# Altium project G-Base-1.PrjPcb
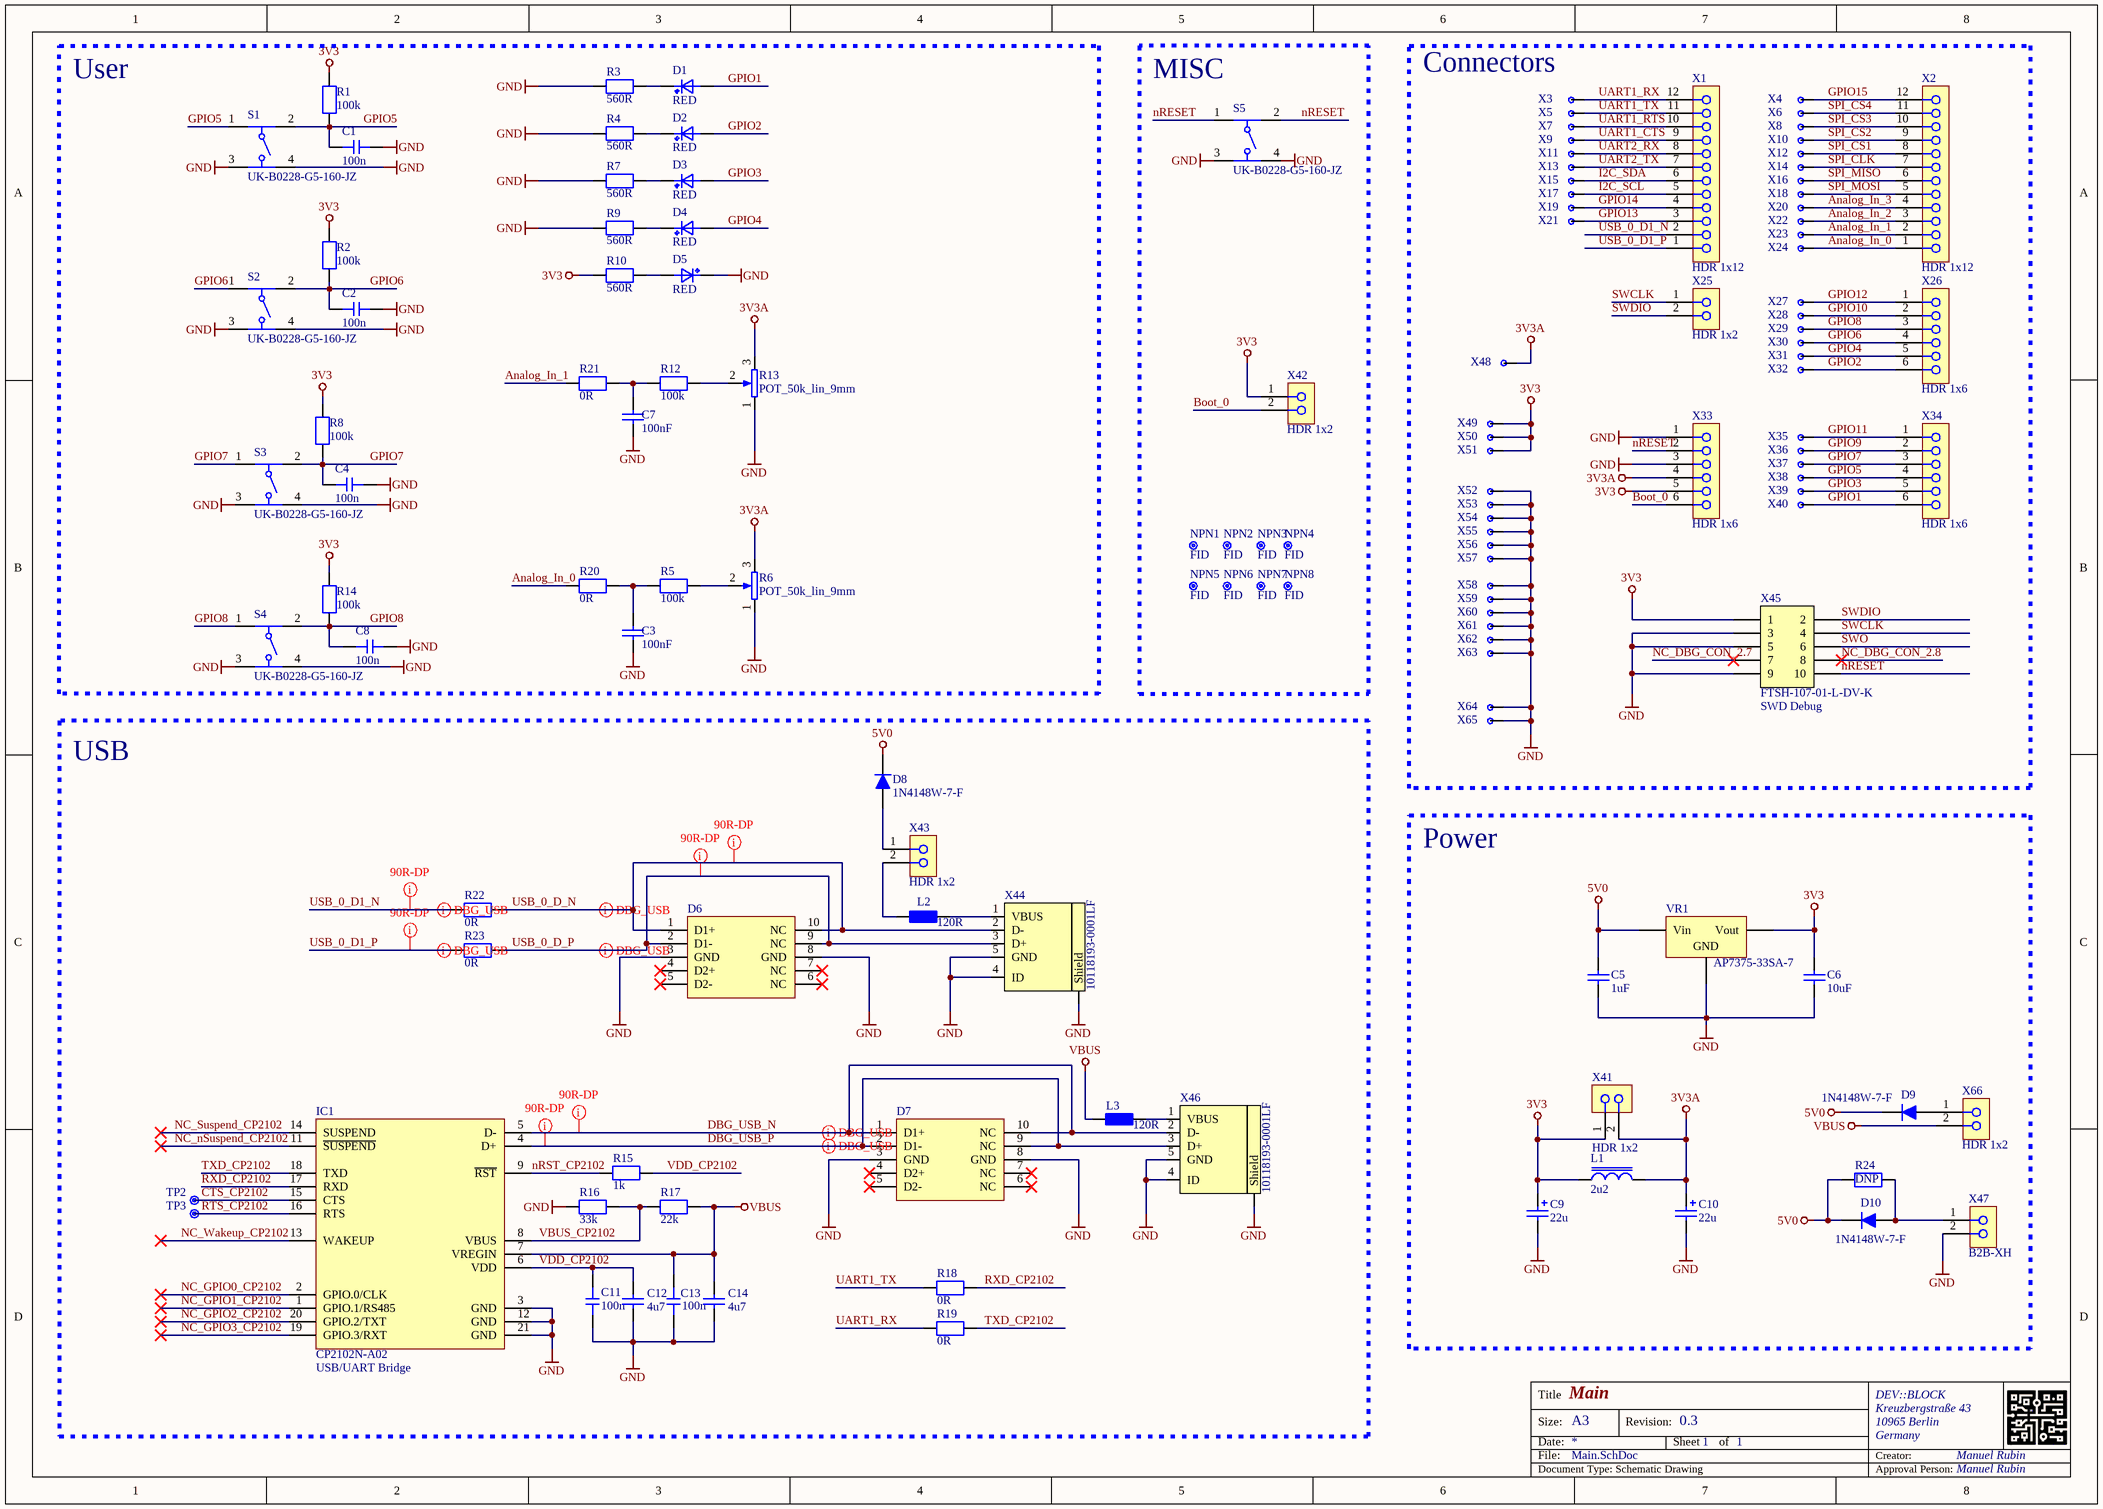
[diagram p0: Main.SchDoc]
Address2: Kreuzbergstraße 43; Address3: 10965 Berlin; Address4: Germany; ApprovalSchematic: Manuel Rubin; CompanyName: DEV::BLOCK; CreatorSchematic: Manuel Rubin; ProjectRevision: 0.3
1 sheet, 133 parts. Net scope: global (net labels, ports and power ports of the same name join across sheets).
Board file: erb-pcb0006.PcbDoc

## Sheet Main.SchDoc: Main
size A3; Author: Manuel Rubin; Revision: 0.1; SheetNumber: 1; SheetTotal: 1

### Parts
C1  100n  [CAPC1608X95N]
C2  100n  [CAPC1608X95N]
C3  100nF  [CAPC1608X95N]
C4  100n  [CAPC1608X95N]
C5  1uF  [CAPC2012X145N]
C6  10uF  [CAPC2012X145N]
C7  100nF  [CAPC1608X95N]
C8  100n  [CAPC1608X95N]
C9  22u  [CAPAE4643X54M]
C10  22u  [CAPAE4643X54M]
C11  100n  [CAPC1608X95N]
C12  4u7  [CAPC1608X95N]
C13  100n  [CAPC1608X95N]
C14  4u7  [CAPC1608X95N]
D1  RED  [WL-SMCW_0805]
D2  RED  [WL-SMCW_0805]
D3  RED  [WL-SMCW_0805]
D4  RED  [WL-SMCW_0805]
D5  RED  [WL-SMCW_0805]
D6  (no value)  [DQA R-PUSON-N10]
D7  (no value)  [DQA R-PUSON-N10]
D8  1N4148W-7-F  [SOD-123]
D9  1N4148W-7-F  [SOD-123]
D10  1N4148W-7-F  [SOD-123]
IC1  CP2102N-A02  DevNote: USB/UART Bridge  [SILABS_CP2102N-A02-GQFN20R]
L1  2u2  [INDP5050X39N]
L2  120R  [INDC1608X95AN]
L3  120R  [INDC1608X95AN]
NPN1  FID  [Fiducial_1mm]
NPN2  FID  [Fiducial_1mm]
NPN3  FID  [Fiducial_1mm]
NPN4  FID  [Fiducial_1mm]
NPN5  FID  [Fiducial_1mm]
NPN6  FID  [Fiducial_1mm]
NPN7  FID  [Fiducial_1mm]
NPN8  FID  [Fiducial_1mm]
R1  100k  [RESC2012X70N]
R2  100k  [RESC2012X70N]
R3  560R  [RESC1608X55N]
R4  560R  [RESC1608X55N]
R5  100k  [RESC2012X70N]
R6  POT_50k_lin_9mm  [PTV09]
R7  560R  [RESC1608X55N]
R8  100k  [RESC2012X70N]
R9  560R  [RESC1608X55N]
R10  560R  [RESC1608X55N]
R12  100k  [RESC2012X70N]
R13  POT_50k_lin_9mm  [PTV09]
R14  100k  [RESC2012X70N]
R15  1k  [RESC1608X55AN]
R16  33k  [RESC1608X55AN]
R17  22k  [RESC1608X55AN]
R18  0R  [RESC1608X55N]
R19  0R  [RESC1608X55N]
R20  0R  [RESC1608X55N]
R21  0R  [RESC1608X55N]
R22  0R  [RESC1608X55N]
R23  0R  [RESC1608X55N]
R24  DNP  [RESC2012X70N]  (no BOM)
S1  UK-B0228-G5-160-JZ  [UK-B0228-G5-160-JZ]
S2  UK-B0228-G5-160-JZ  [UK-B0228-G5-160-JZ]
S3  UK-B0228-G5-160-JZ  [UK-B0228-G5-160-JZ]
S4  UK-B0228-G5-160-JZ  [UK-B0228-G5-160-JZ]
S5  UK-B0228-G5-160-JZ  [UK-B0228-G5-160-JZ]
TP2  TP 0.7mm  [TP_0.7mm]  (value not drawn)  (no BOM)
TP3  TP 0.7mm  [TP_0.7mm]  (value not drawn)  (no BOM)
VR1  AP7375-33SA-7  [SOT95P280X135-3N_123]
X1  HDR 1x12  [61301211821_NO]
X2  HDR 1x12  [61301211821_NO]
X3  PAD  [PAD_1.1_1.6]  (value not drawn)  (net tie, no BOM)
X4  PAD  [PAD_1.1_1.6]  (value not drawn)  (net tie, no BOM)
X5  PAD  [PAD_1.1_1.6]  (value not drawn)  (net tie, no BOM)
X6  PAD  [PAD_1.1_1.6]  (value not drawn)  (net tie, no BOM)
X7  PAD  [PAD_1.1_1.6]  (value not drawn)  (net tie, no BOM)
X8  PAD  [PAD_1.1_1.6]  (value not drawn)  (net tie, no BOM)
X9  PAD  [PAD_1.1_1.6]  (value not drawn)  (net tie, no BOM)
X10  PAD  [PAD_1.1_1.6]  (value not drawn)  (net tie, no BOM)
X11  PAD  [PAD_1.1_1.6]  (value not drawn)  (net tie, no BOM)
X12  PAD  [PAD_1.1_1.6]  (value not drawn)  (net tie, no BOM)
X13  PAD  [PAD_1.1_1.6]  (value not drawn)  (net tie, no BOM)
X14  PAD  [PAD_1.1_1.6]  (value not drawn)  (net tie, no BOM)
X15  PAD  [PAD_1.1_1.6]  (value not drawn)  (net tie, no BOM)
X16  PAD  [PAD_1.1_1.6]  (value not drawn)  (net tie, no BOM)
X17  PAD  [PAD_1.1_1.6]  (value not drawn)  (net tie, no BOM)
X18  PAD  [PAD_1.1_1.6]  (value not drawn)  (net tie, no BOM)
X19  PAD  [PAD_1.1_1.6]  (value not drawn)  (net tie, no BOM)
X20  PAD  [PAD_1.1_1.6]  (value not drawn)  (net tie, no BOM)
X21  PAD  [PAD_1.1_1.6]  (value not drawn)  (net tie, no BOM)
X22  PAD  [PAD_1.1_1.6]  (value not drawn)  (net tie, no BOM)
X23  PAD  [PAD_1.1_1.6]  (value not drawn)  (net tie, no BOM)
X24  PAD  [PAD_1.1_1.6]  (value not drawn)  (net tie, no BOM)
X25  HDR 1x2  [61300211821_NO]
X26  HDR 1x6  [61300611821_NO]
X27  PAD  [PAD_1.1_1.6]  (value not drawn)  (net tie, no BOM)
X28  PAD  [PAD_1.1_1.6]  (value not drawn)  (net tie, no BOM)
X29  PAD  [PAD_1.1_1.6]  (value not drawn)  (net tie, no BOM)
X30  PAD  [PAD_1.1_1.6]  (value not drawn)  (net tie, no BOM)
X31  PAD  [PAD_1.1_1.6]  (value not drawn)  (net tie, no BOM)
X32  PAD  [PAD_1.1_1.6]  (value not drawn)  (net tie, no BOM)
X33  HDR 1x6  [61300611821_NO]
X34  HDR 1x6  [61300611821_NO]
X35  PAD  [PAD_1.1_1.6]  (value not drawn)  (net tie, no BOM)
X36  PAD  [PAD_1.1_1.6]  (value not drawn)  (net tie, no BOM)
X37  PAD  [PAD_1.1_1.6]  (value not drawn)  (net tie, no BOM)
X38  PAD  [PAD_1.1_1.6]  (value not drawn)  (net tie, no BOM)
X39  PAD  [PAD_1.1_1.6]  (value not drawn)  (net tie, no BOM)
X40  PAD  [PAD_1.1_1.6]  (value not drawn)  (net tie, no BOM)
X41  HDR 1x2  [CON_HEADER2.54_1x2W]
X42  HDR 1x2  [CON_HEADER2.54_1x2W]
X43  HDR 1x2  [CON_HEADER2.54_1x2W]
X44  10118193-0001LF  [USB-Micro-B-RA-SMD-PiP]
X45  FTSH-107-01-L-DV-K  DevNote: SWD Debug  [HDR_2x5-SMD-1.27mm-K]
X46  10118193-0001LF  [USB-Micro-B-RA-SMD-PiP]
X47  B2B-XH  [JST_B2B-XH-A_(LF)(SN)]
X48  PAD  [PAD_1.1_1.6]  (value not drawn)  (net tie, no BOM)
X49  PAD  [PAD_1.1_1.6]  (value not drawn)  (net tie, no BOM)
X50  PAD  [PAD_1.1_1.6]  (value not drawn)  (net tie, no BOM)
X51  PAD  [PAD_1.1_1.6]  (value not drawn)  (net tie, no BOM)
X52  PAD  [PAD_1.1_1.6]  (value not drawn)  (net tie, no BOM)
X53  PAD  [PAD_1.1_1.6]  (value not drawn)  (net tie, no BOM)
X54  PAD  [PAD_1.1_1.6]  (value not drawn)  (net tie, no BOM)
X55  PAD  [PAD_1.1_1.6]  (value not drawn)  (net tie, no BOM)
X56  PAD  [PAD_1.1_1.6]  (value not drawn)  (net tie, no BOM)
X57  PAD  [PAD_1.1_1.6]  (value not drawn)  (net tie, no BOM)
X58  PAD  [PAD_1.1_1.6]  (value not drawn)  (net tie, no BOM)
X59  PAD  [PAD_1.1_1.6]  (value not drawn)  (net tie, no BOM)
X60  PAD  [PAD_1.1_1.6]  (value not drawn)  (net tie, no BOM)
X61  PAD  [PAD_1.1_1.6]  (value not drawn)  (net tie, no BOM)
X62  PAD  [PAD_1.1_1.6]  (value not drawn)  (net tie, no BOM)
X63  PAD  [PAD_1.1_1.6]  (value not drawn)  (net tie, no BOM)
X64  PAD  [PAD_1.1_1.6]  (value not drawn)  (net tie, no BOM)
X65  PAD  [PAD_1.1_1.6]  (value not drawn)  (net tie, no BOM)
X66  HDR 1x2  [CON_HEADER2.54_1x2W]

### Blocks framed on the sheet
User: C1-C4 C7 C8 D1-D5 R1-R10 R12-R14 R20 R21 S1-S4
MISC: NPN1-NPN8 S5 X42
Connectors: X1-X40 X45 X48-X65
USB: C11-C14 D6-D8 IC1 L2 L3 R15-R19 R22 R23 TP2 TP3 X43 X44 X46
Power: C5 C6 C9 C10 D9 D10 L1 R24 VR1 X41 X47 X66

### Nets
3V3: C6.1 C9.1 L1.1 R1.2 R2.2 R8.2 R10.1 R14.2 VR1.2(Vout) X33.5 X41.1 X42.1 X45.1 X49.1 X50.1 X51.1
3V3A: C10.1 L1.2 R6.3 R13.3 X33.4 X41.2 X48.1
5V0: C5.1 D8.2(K) D9.2(K) D10.2(K) R24.1 VR1.1(Vin)
GND: C1.2 C2.2 C3.2 C4.2 C5.2 C6.2 C7.2 C8.2 C9.2 C10.2 C11.1 C12.1 C13.1 C14.1 D5.K D6.3(GND) D6.8(GND) D7.3(GND) D7.8(GND) IC1.3(GND) IC1.12(GND) IC1.21(GND) R3.1 R4.1 R6.1 R7.1 R9.1 R13.1 R16.2 S1.3 S1.4 S2.3 S2.4 S3.3 S3.4 S4.3 S4.4 S5.3 S5.4 VR1.3(GND) X33.1 X33.3 X44.4(ID) X44.5(GND) X44.6(Shield) X45.3 X45.5 X45.9 X46.4(ID) X46.5(GND) X46.6(Shield) X47.2 X52.1 X53.1 X54.1 X55.1 X56.1 X57.1 X58.1 X59.1 X60.1 X61.1 X62.1 X63.1 X64.1 X65.1
VBUS: C13.2 C14.2 IC1.7(VREGIN) L3.1 R17.1 X66.2
Analog_In_0: R20.2 X2.1 X24.1
Analog_In_1: R21.2 X2.2 X23.1
Analog_In_2: X2.3 X22.1
Analog_In_3: X2.4 X20.1
Boot_0: X33.6 X42.2
CTS_CP2102: IC1.15(CTS) TP2.1
DBG_USB_N: D7.1(D1+) D7.10(NC) IC1.5(D-) X46.2(D-)
DBG_USB_P: D7.2(D1-) D7.9(NC) IC1.4(D+) X46.3(D+)
GPIO1: D1.A X34.6 X40.1
GPIO2: D2.A X26.6 X32.1
GPIO3: D3.A X34.5 X39.1
GPIO4: D4.A X26.5 X31.1
GPIO5: C1.1 R1.1 S1.1 S1.2 X34.4 X38.1
GPIO6: C2.1 R2.1 S2.1 S2.2 X26.4 X30.1
GPIO7: C4.1 R8.1 S3.1 S3.2 X34.3 X37.1
GPIO8: C8.1 R14.1 S4.1 S4.2 X26.3 X29.1
GPIO9: X34.2 X36.1
GPIO10: X26.2 X28.1
GPIO11: X34.1 X35.1
GPIO12: X26.1 X27.1
GPIO13: X1.3 X21.1
GPIO14: X1.4 X19.1
GPIO15: X2.12 X4.1
I2C_SCL: X1.5 X17.1
I2C_SDA: X1.6 X15.1
NC_DBG_CON_2.7: X45.7
NC_DBG_CON_2.8: X45.8
NC_GPIO0_CP2102: IC1.2(GPIO.0/CLK)
NC_GPIO1_CP2102: IC1.1(GPIO.1/RS485)
NC_GPIO2_CP2102: IC1.20(GPIO.2/TXT)
NC_GPIO3_CP2102: IC1.19(GPIO.3/RXT)
NC_nSuspend_CP2102: IC1.11(~{SUSPEND})
NC_Suspend_CP2102: IC1.14(SUSPEND)
NC_Wakeup_CP2102: IC1.13(WAKEUP)
nRESET: S5.1 S5.2 X33.2 X45.10
nRST_CP2102: IC1.9(~{RST}) R15.2
RTS_CP2102: IC1.16(RTS) TP3.1
RXD_CP2102: IC1.17(RXD) R18.1
SPI_CLK: X2.7 X14.1
SPI_CS1: X2.8 X12.1
SPI_CS2: X2.9 X10.1
SPI_CS3: X2.10 X8.1
SPI_CS4: X2.11 X6.1
SPI_MISO: X2.6 X16.1
SPI_MOSI: X2.5 X18.1
SWCLK: X25.1 X45.4
SWDIO: X25.2 X45.2
SWO: X45.6
TXD_CP2102: IC1.18(TXD) R19.1
UART1_CTS: X1.9 X9.1
UART1_RTS: X1.10 X7.1
UART1_RX: R19.2 X1.12 X3.1
UART1_TX: R18.2 X1.11 X5.1
UART2_RX: X1.8 X11.1
UART2_TX: X1.7 X13.1
USB_0_D1_N: R22.2 X1.2
USB_0_D1_P: R23.2 X1.1
USB_0_D_N: D6.1(D1+) D6.10(NC) R22.1 X44.2(D-)
USB_0_D_P: D6.2(D1-) D6.9(NC) R23.1 X44.3(D+)
VBUS_CP2102: IC1.8(VBUS) R16.1 R17.2
VDD_CP2102: C11.2 C12.2 IC1.6(VDD) R15.1
NetC3_1: C3.1 R5.1 R20.1
NetC7_1: C7.1 R12.1 R21.1
NetD1_K: D1.K R3.2
NetD2_K: D2.K R4.2
NetD3_K: D3.K R7.2
NetD4_K: D4.K R9.2
NetD5_A: D5.A R10.2
NetD8_1: D8.1(A) X43.1
NetD9_1: D9.1(A) X66.1
NetD10_1: D10.1(A) R24.2 X47.1
NetL2_1: L2.1 X43.2
NetL2_2: L2.2 X44.1(VBUS)
NetL3_2: L3.2 X46.1(VBUS)
NetR5_2: R5.2 R6.2
NetR12_2: R12.2 R13.2

Not connected (* = marked no-connect by the designer): D6 4(D2+)* 5(D2-)* 6(NC)* 7(NC)*; D7 4(D2+)* 5(D2-)* 6(NC)* 7(NC)*

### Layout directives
differential pair: DBG_USB_N, DBG_USB_P, USB_0_D1_N, USB_0_D1_P, USB_0_D_N, USB_0_D_P
net class 90R-DP: DBG_USB_N, DBG_USB_P, USB_0_D1_N, USB_0_D1_P, USB_0_D_N, USB_0_D_P

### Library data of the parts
C1 C2 C4 C8 C11 C13 = C_100n_50V_0603: 100n_50V; Manufacturer: AVX; Manufacturer Part Number: 06031C104KAT2A; Voltage Rating: 50V; Tolerance: +-10%; Alternatives allowed: YES; Notes: X7R, 0603; Value: 100nF
C3 C7 = CAP_100nF_0603: Multilayer Ceramic Capacitors MLCC - SMD/SMT, 100nF; Manufacturer: YAGEO; Manufacturer Part Number: CC0603KRX7R9BB104; Voltage Rating: 50VDC; Tolerance: 10%; Alternatives allowed: yes
C5 = CAP_1uF_0805: Multilayer Ceramic Capacitors MLCC - SMD/SMT, 1uF; Manufacturer: Samsung Electro-Mechanics; Manufacturer Part Number: CL21B105KBFNNNE; Tolerance: 10%; Voltage Rating: 50V; Alternatives allowed: yes
C6 = CAP_10uF_0805: Multilayer Ceramic Capacitors MLCC - SMD/SMT, 10uF; Manufacturer: Samsung Electro-Mechanics; Manufacturer Part Number: CL21A106KAYNNNE; Tolerance: 10%; Voltage Rating: 25V; Alternatives allowed: yes
C9 C10 = CAP_22u: Aluminium Electrolytic Capacitors - SMD 22UF 16V HA SMD; Manufacturer: Panasonic; Manufacturer Part Number: EEE-HAC220WAR; Tolerance: 20%; Alternatives allowed: NO
C12 C14 = CAP_4u7_0603: 16V 4.7uF X5R ±10% 0603 Multilayer Ceramic Capacitors MLCC - SMD/SMT ROHS; Manufacturer: Murata Electronics; Manufacturer Part Number: GRM188C81C475KE11D; Voltage Rating: 16VDC; Alternatives allowed: yes
D1 = LED_0805_RED_AK: Standard LEDs - SMD WL-SMCW SMDMono TpVw Waterclr 0805 Red; Manufacturer: Wurth Elektronik; Manufacturer Part Number: 150080RS75000; Voltage Rating: 2.0; Alternatives allowed: YES; DevNote: LED1
D2 = LED_0805_RED_AK: Standard LEDs - SMD WL-SMCW SMDMono TpVw Waterclr 0805 Red; Manufacturer: Wurth Elektronik; Manufacturer Part Number: 150080RS75000; Voltage Rating: 2.0; Alternatives allowed: YES; DevNote: LED2
D3 = LED_0805_RED_AK: Standard LEDs - SMD WL-SMCW SMDMono TpVw Waterclr 0805 Red; Manufacturer: Wurth Elektronik; Manufacturer Part Number: 150080RS75000; Voltage Rating: 2.0; Alternatives allowed: YES; DevNote: LED3
D4 = LED_0805_RED_AK: Standard LEDs - SMD WL-SMCW SMDMono TpVw Waterclr 0805 Red; Manufacturer: Wurth Elektronik; Manufacturer Part Number: 150080RS75000; Voltage Rating: 2.0; Alternatives allowed: YES; DevNote: LED4
D5 = LED_0805_RED_AK: Standard LEDs - SMD WL-SMCW SMDMono TpVw Waterclr 0805 Red; Manufacturer: Wurth Elektronik; Manufacturer Part Number: 150080RS75000; Voltage Rating: 2.0; Alternatives allowed: YES
D6 D7 = TPD4EUSB30DQAR: 2-, 4-Channel ESD Protection for Super-Speed USB 3.0 Interface; Manufacturer: Texas Instruments; Alternatives allowed: NO
D8-D10 = 1N4148W-7-F: Diodes - General Purpose, Power, Switching SURFACE MOUNT FAST SWITCHING DIODE 2A; Manufacturer: Diodes Incorporated
IC1 = IC_CP2102N-A02-QFN20: USB Interface IC USBXpress - USB to UART Bridge QFN28; Manufacturer: Silicon Labs; Manufacturer Part Number: CP2102N-A02-GQFN20R; Alternatives allowed: NO
L1 = IND_2u2_3.8A: Fixed Inductors 2.2uH 3.8A; Manufacturer: Bourns; Manufacturer Part Number: SRN5040TA-2R2M; Voltage Rating: 50V; Tolerance: 10%; Alternatives allowed: yes
L2 L3 = FB_600R_0603: Chip Bead Inductors for Power Lines; Manufacturer: Taiyo Yuden; Manufacturer Part Number: FBMH1608HL121-T; Alternatives allowed: YES; Notes: 0603, 1,2A
NPN1-NPN8 = Fiducial_1mm
R1 R2 R5 R8 R12 R14 = RES_100k_0805: Thick Film Resistors - SMD 1/8watt 100Kohms 1% 100ppm; Manufacturer: Vishay / Dale; Manufacturer Part Number: CRCW0805100KFKEA; Voltage Rating: 150V; Alternatives allowed: YES
R3 R4 R7 R9 R10 = RES_560R_0603: Thick Film Resistors - SMD 560 Ohms 125 mW 0603; Manufacturer: ROHM Semicon; Manufacturer Part Number: MCR03ERTF5600; Voltage Rating: 150V; Tolerance: 1%; Alternatives allowed: YES
R6 R13 = POT_50k_lin_9mm: PTV09A-4020F-A203 50k, 20mm; Manufacturer: Bourns; Manufacturer Part Number: PTV09A-5020F-A503; Tolerance: 20%
R15 = RES_1k_0603: Thick Film Resistors - SMD 1 kOhms 100mW 0603 1%; Manufacturer: Yageo; Manufacturer Part Number: RC0603FR-071KL; Voltage Rating: 75V; Alternatives allowed: YES
R16 = RES_33k_0603: Thick Film Resistors - SMD 33 kOhms 100 mW 0603 5%; Manufacturer: YAGEO; Manufacturer Part Number: RC0603JR-0733KL; Voltage Rating: 50V; Tolerance: 1%; Alternatives allowed: YES
R17 = RES_22k_0603: Thick Film Resistors - SMD 22kOhms 1/10W 0603 1%; Manufacturer: YAGEO; Manufacturer Part Number: RC0603FR-7W22KL; Voltage Rating: 75V; Alternatives allowed: YES
R18-R23 = RES_0R_0603: Thick Film Resistors - SMD 1/10watt ZEROohm Jumper; Manufacturer: Vishay; Manufacturer Part Number: CRCW06030000Z0EA; Voltage Rating: 75V; Tolerance: 1%; Alternatives allowed: YES
R24 = RES_DNF_0805: Resistor SMD 0805 - not populated
S1 = SW_UK-B0228-G5-160-JZ: No NO Gull Wing 50mA 6mm 100MΩ 100000 12V 160gf@±50gf -20℃~+70℃ 6mm 5mm Black Round Button Brick nogging SPST SMD Tactile Switches ROHS; Manufacturer: USAKRO; DevNote: BTN1
S2 = SW_UK-B0228-G5-160-JZ: No NO Gull Wing 50mA 6mm 100MΩ 100000 12V 160gf@±50gf -20℃~+70℃ 6mm 5mm Black Round Button Brick nogging SPST SMD Tactile Switches ROHS; Manufacturer: USAKRO; DevNote: BTN2
S3 = SW_UK-B0228-G5-160-JZ: No NO Gull Wing 50mA 6mm 100MΩ 100000 12V 160gf@±50gf -20℃~+70℃ 6mm 5mm Black Round Button Brick nogging SPST SMD Tactile Switches ROHS; Manufacturer: USAKRO; DevNote: BTN3
S4 = SW_UK-B0228-G5-160-JZ: No NO Gull Wing 50mA 6mm 100MΩ 100000 12V 160gf@±50gf -20℃~+70℃ 6mm 5mm Black Round Button Brick nogging SPST SMD Tactile Switches ROHS; Manufacturer: USAKRO; DevNote: BTN4
S5 = SW_UK-B0228-G5-160-JZ: No NO Gull Wing 50mA 6mm 100MΩ 100000 12V 160gf@±50gf -20℃~+70℃ 6mm 5mm Black Round Button Brick nogging SPST SMD Tactile Switches ROHS; Manufacturer: USAKRO; DevNote: Reset
TP2 TP3 = MISC_Test Pad 0.7mm: Test Pad surface mount; Notes: Test Pad Only; Alternatives allowed: NO
VR1 = IC_AP7375-33SA-7: 3.3V, 300mA LDO Spannungs-Regulator LDO High Voltage Standard SOT23 T&R 3K; Manufacturer: Diodes Incorporated
X1 = CON_HEADER_1X12_FEMALE_NO: Board-to-Board-Steckverbinder, 2.54 mm, 12 Kontakt(e), Stiftleiste 1-Reihig; Manufacturer: WE; Manufacturer Part Number: 61301211821; Alternatives allowed: YES; DevNote: Board Connector
X2 = CON_HEADER_1X12_FEMALE_NO: Board-to-Board-Steckverbinder, 2.54 mm, 12 Kontakt(e), Stiftleiste 1-Reihig; Manufacturer: WE; Manufacturer Part Number: 61301211821; Alternatives allowed: YES
X3-X24 X27-X32 X35-X40 X48-X65 = PAD_2.54
X25 = CON_HEADER_1X2_FEMALE_NO: Board-to-Board-Steckverbinder, 2.54 mm, 2 Kontakt(e), Stiftleiste 1-Reihig; Manufacturer: WE; Manufacturer Part Number: 61300211821; Alternatives allowed: YES
X26 X33 X34 = CON_HEADER_1X6_FEMALE_NO: Board-to-Board-Steckverbinder, 2.54 mm, 6 Kontakt(e), Stiftleiste 1-Reihig; Manufacturer: WE; Manufacturer Part Number: 61300611821; Alternatives allowed: YES
X41 = CON_HEADER_1X2: Board-to-Board-Steckverbinder, 2.54 mm, 2 Kontakt(e), Stiftleiste 1-Reihig; Manufacturer: Samtec; Manufacturer Part Number: TSW-102-07-T-S; Alternatives allowed: YES; DevNote: Filter Bypass
X42 = CON_HEADER_1X2: Board-to-Board-Steckverbinder, 2.54 mm, 2 Kontakt(e), Stiftleiste 1-Reihig; Manufacturer: Samtec; Manufacturer Part Number: TSW-102-07-T-S; Alternatives allowed: YES; DevNote: Boot0
X43 = CON_HEADER_1X2: Board-to-Board-Steckverbinder, 2.54 mm, 2 Kontakt(e), Stiftleiste 1-Reihig; Manufacturer: Samtec; Manufacturer Part Number: TSW-102-07-T-S; Alternatives allowed: YES; DevNote: VBusSel2
X44 = CON_MiniUSB-AB-SMT: MicroUSB-B-SMT; Manufacturer: Amphenol ICC (FCI); DevNote: USB-MCU
X45 = CON_2x5_SMD_1.27mm: Pin Header 2x5, 1.27mm (50mil), SMD, Keying Shroud; Manufacturer: Samtec; Manufacturer Part Number: FTSH-105-01-L-DV-K
X46 = CON_MiniUSB-AB-SMT: MicroUSB-B-SMT; Manufacturer: Amphenol ICC (FCI); DevNote: USB-Debug
X47 = CON_JST_B2B-XH: Connector Header Through Hole 2 position 0.098" (2.50mm); Manufacturer: JST; Manufacturer Part Number: B2B-XH-A (LF)(SN); Alternatives allowed: YES; DevNote: Extern-PWR
X66 = CON_HEADER_1X2: Board-to-Board-Steckverbinder, 2.54 mm, 2 Kontakt(e), Stiftleiste 1-Reihig; Manufacturer: Samtec; Manufacturer Part Number: TSW-102-07-T-S; Alternatives allowed: YES; DevNote: VBusSel1

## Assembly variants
EmptyBoard: not fitted C1 C2 C3 C4 C5 C6 C7 C8 C9 C10 C11 C12 C13 C14 D1 D2 D3 D4 D5 D6 D7 D8 D9 D10 IC1 L1 L2 L3 NPN1 NPN2 NPN3 NPN4 NPN5 NPN6 NPN7 NPN8 R1 R2 R3 R4 R5 R6 R7 R8 R9 R10 R12 R13 R14 R15 R16 R17 R18 R19 R20 R21 R22 R23 R24 S1 S2 S3 S4 S5 TP2 TP3 VR1 X1 X2 X3 X4 X5 X6 X7 X8 X9 X10 X11 X12 X13 X14 X15 X16 X17 X18 X19 X20 X21 X22 X23 X24 X25 X26 X27 X28 X29 X30 X31 X32 X33 X34 X35 X36 X37 X38 X39 X40 X41 X42 X43 X44 X45 X46 X47 X48 X49 X50 X51 X52 X53 X54 X55 X56 X57 X58 X59 X60 X61 X62 X63 X64 X65 X66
